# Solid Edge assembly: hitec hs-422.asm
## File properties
Author: nakano
Template: iso metric assembly.asm
Last saved by: nakano
Revision: 6
Application: Solid Edge
Username: nakano
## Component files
servo body.par
servo output.par
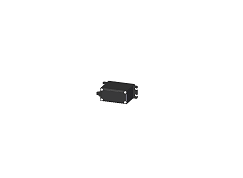
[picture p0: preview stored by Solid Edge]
